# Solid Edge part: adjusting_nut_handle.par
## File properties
Title: Solid Edge 20
Author: vicky raina
Template: Normal.par
Last saved by: Robert a Rhodes jr
Revision: 4
Application: Solid Edge
Material: aluminum
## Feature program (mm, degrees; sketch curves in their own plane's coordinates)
sketch for "unnamed Protrusion 1" plane through (0, 0, 0) normal (0, -1, 0) x-axis (1, 0, 0)
  circle centre (0, 0) radius 9.5123
extrude "unnamed Protrusion 1" add finite 127 symmetric
chamfer "unnamed Chamfer 1"
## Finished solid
Body 1: solid body, 5 faces, 4 edges, 0 vertices.
  Faces by surface: cone 2, plane 2, cylinder 1
  Edges by curve: circle 4
Bounding box of the edges (mm): 19.025 x 127.000 x 19.025, from (-9.5123, -63.5, -9.5123) to (9.5123, 63.5, 9.5123).
Cylindrical faces by radius (mm): R9.5123 x1
Conical faces (half-angle, radius in mm at the cone's reference point): 45 deg R7.9375 x1, 45 deg R9.5123 x1
Planar faces by outward normal: +y 1, -y 1
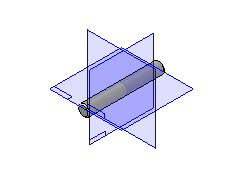
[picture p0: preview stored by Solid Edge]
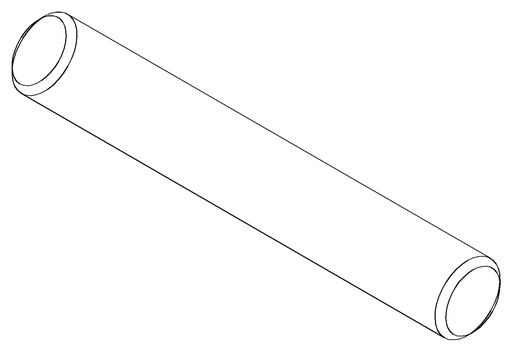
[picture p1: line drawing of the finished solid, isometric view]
